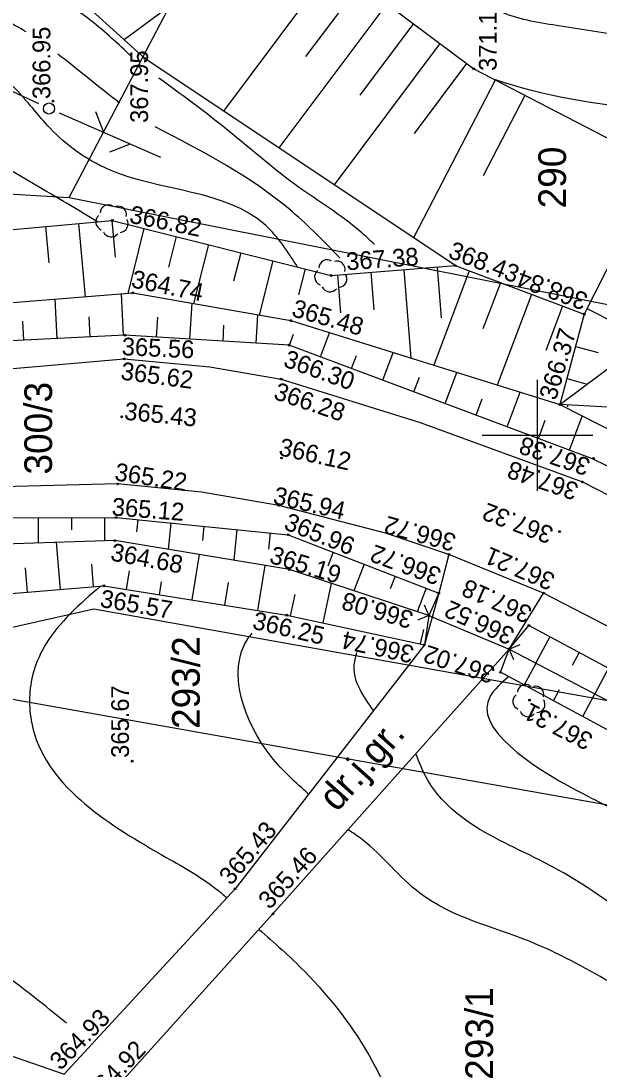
# Model space of a CAD drawing. Extents: x 4635329 to 4651863, y 5356628 to 5367582.
# Drawn here: x 4651263.7 to 4651289.79, y 5356677.75 to 5356725.05 of the extents above; entities that cross this region are included whole.
import ezdxf

# ---------------------------------------------------------------- set-up
doc = ezdxf.new("R2010")
doc.units = 0
for name, color, linetype in [('Level 20', 7, 'Continuous'), ('Level 21', 7, 'Continuous'), ('Level 24', 7, 'Continuous'), ('Level 32', 7, 'Continuous'), ('Level 4', 7, 'Continuous'), ('Level 44', 7, 'Continuous'), ('Level 45', 7, 'Continuous'), ('Level 46', 7, 'Continuous'), ('Level 48', 7, 'Continuous'), ('Level 5', 7, 'Continuous'), ('Level 50', 7, 'Continuous'), ('Level 55', 7, 'Continuous'), ('Level 60', 7, 'Continuous')]:
    doc.layers.add(name, color=color, linetype=linetype)

msp = doc.modelspace()

# ---------------------------------------------------------------- linework, layer by layer
at = {"layer": 'Level 20'}
for p, q in [((4651255.835, 5356708.727), (4651268.355, 5356709.797)), ((4651289.035, 5356704.247), (4651300.075, 5356698.607))]:
    msp.add_line(p, q, dxfattribs=at)
for points in [[(4651268.355, 5356709.797), (4651272.22, 5356709.442), (4651275.445, 5356708.887)], [(4651275.445, 5356708.887), (4651281.72, 5356706.931), (4651289.035, 5356704.247)], [(4651311.985, 5356685.667), (4651297.855, 5356693.767), (4651287.285, 5356699.227), (4651283.015, 5356700.977), (4651280.145, 5356701.933), (4651275.335, 5356703.187), (4651271.856, 5356703.778), (4651268.065, 5356704.157), (4651257.665, 5356703.887), (4651250.625, 5356702.417), (4651229.275, 5356695.327), (4651226.835, 5356694.217), (4651221.145, 5356692.917), (4651218.085, 5356691.717)], [(4651283.015, 5356700.977), (4651282.555, 5356699.227), (4651281.905, 5356696.897), (4651273.365, 5356685.887), (4651265.645, 5356677.517)], [(4651267.255, 5356676.097), (4651275.075, 5356684.757), (4651285.735, 5356696.707), (4651287.285, 5356699.227)], [(4651256.195, 5356680.807), (4651265.645, 5356677.517)]]:
    msp.add_lwpolyline(points, dxfattribs=at)
at = {"layer": 'Level 24'}
for p, q in [((4651281.903, 5356698.707), (4651282.105, 5356698.217)), ((4651282.105, 5356698.217), (4651281.615, 5356698.015)), ((4651282.105, 5356698.217), (4651285.735, 5356696.707)), ((4651285.735, 5356696.707), (4651286.225, 5356696.909)), ((4651285.937, 5356696.217), (4651285.735, 5356696.707))]:
    msp.add_line(p, q, dxfattribs=at)
at = {"layer": 'Level 32'}
for p, q in [((4651264.512, 5356721.308), (4651259.978, 5356723.417)), ((4651265.423, 5356720.897), (4651270.006, 5356718.896)), ((4651267.446, 5356720.014), (4651267.081, 5356720.945)), ((4651268.631, 5356719.496), (4651267.7, 5356719.131))]:
    msp.add_line(p, q, dxfattribs=at)
msp.add_circle((4651264.965, 5356721.097), 0.25, dxfattribs=at)
at = {"layer": 'Level 4'}
for p, q in [((4651265.88, 5356717.076), (4651276.761, 5356737.838)), ((4651262.484, 5356717.287), (4651265.88, 5356717.076)), ((4651265.88, 5356717.076), (4651293.053, 5356711.679)), ((4651266.997, 5356698.5), (4651255.225, 5356695.887)), ((4651294.579, 5356693.592), (4651266.997, 5356698.5)), ((4651255.225, 5356695.887), (4651299.165, 5356688.087))]:
    msp.add_line(p, q, dxfattribs=at)
at = {"layer": 'Level 44'}
for centre in [(4651269.285, 5356723.357), (4651284.135, 5356722.887), (4651265.147, 5356721.43), (4651267.825, 5356716.047), (4651277.695, 5356713.567), (4651283.295, 5356714.007), (4651268.755, 5356712.777), (4651289.115, 5356711.817), (4651275.875, 5356711.527), (4651268.385, 5356710.867), (4651275.805, 5356710.417), (4651268.355, 5356709.797), (4651275.445, 5356708.887), (4651288.015, 5356707.737), (4651268.245, 5356707.187), (4651275.465, 5356705.327), (4651289.535, 5356705.308), (4651268.065, 5356704.157), (4651289.035, 5356704.247), (4651275.335, 5356703.187), (4651267.995, 5356702.637), (4651275.755, 5356701.867), (4651288.005, 5356702.007), (4651267.935, 5356701.597), (4651283.015, 5356700.977), (4651275.815, 5356700.297), (4651267.445, 5356699.557), (4651282.555, 5356699.227), (4651287.285, 5356699.227), (4651275.705, 5356698.237), (4651282.105, 5356698.217), (4651286.625, 5356697.767), (4651281.905, 5356696.897), (4651285.735, 5356696.707), (4651285.335, 5356695.657), (4651286.645, 5356694.397), (4651268.725, 5356691.647), (4651273.365, 5356685.887), (4651275.075, 5356684.757)]:
    msp.add_circle(centre, 0.04, dxfattribs=at)
at = {"layer": 'Level 46'}
for points in [[(4651267.161, 5356715.987), (4651264.708, 5356717.442), (4651260.614, 5356719.868), (4651257.43, 5356722.141), (4651254.792, 5356725.021), (4651252.517, 5356728.872), (4651246.741, 5356739.5), (4651245.898, 5356740.725)], [(4651298.334, 5356723.071), (4651293.949, 5356723.874), (4651287.864, 5356724.843), (4651285.317, 5356725.479), (4651282.527, 5356727.511), (4651276.752, 5356731.958), (4651274.72, 5356734.595), (4651272.415, 5356737.688), (4651271.657, 5356740.507), (4651271.694, 5356740.701)], [(4651263.931, 5356724.554), (4651261.972, 5356725.806), (4651257.58, 5356731.092)], [(4651268.687, 5356723.452), (4651266.865, 5356725.056), (4651263.408, 5356727.482), (4651263.267, 5356727.595)], [(4651276.186, 5356713.946), (4651274.753, 5356715.814), (4651267.627, 5356718.36), (4651265.018, 5356720.21), (4651263.442, 5356721.998), (4651259.59, 5356724.848), (4651257.237, 5356726.91)], [(4651268.154, 5356721.342), (4651268.067, 5356721.41), (4651265.371, 5356723.557)], [(4651279.659, 5356714.965), (4651278.996, 5356715.567), (4651276.206, 5356717.568), (4651272.809, 5356720.297), (4651269.931, 5356722.46)], [(4651295.563, 5356720.909), (4651292.254, 5356721.058), (4651285.582, 5356722.24), (4651285.048, 5356722.414)], [(4651278.086, 5356714.362), (4651275.943, 5356716.443), (4651269.759, 5356720.271)], [(4651267.298, 5356699.545), (4651264.801, 5356696.886), (4651264.194, 5356695.37), (4651264.255, 5356693.066), (4651270.259, 5356687.306), (4651272.625, 5356685.79), (4651272.99, 5356685.481)], [(4651276.684, 5356690.165), (4651274.991, 5356691.857), (4651273.96, 5356697.193), (4651274.134, 5356697.423)], [(4651279.608, 5356693.936), (4651278.738, 5356695.917), (4651278.857, 5356696.551)], [(4651285.707, 5356695.457), (4651284.877, 5356694.586), (4651288.759, 5356690.341), (4651291.246, 5356689.007), (4651295.31, 5356684.945), (4651298.181, 5356680.494)], [(4651300.394, 5356650.538), (4651298.071, 5356657.119), (4651297.283, 5356664.395), (4651297.525, 5356670.398), (4651297.222, 5356675.491), (4651291.339, 5356684.404), (4651287.093, 5356687.193), (4651283.575, 5356689.133), (4651281.998, 5356690.892), (4651281.523, 5356691.985)], [(4651265.764, 5356679.82), (4651263.304, 5356681.756), (4651255.783, 5356687.85), (4651255.142, 5356688.646)], [(4651290.286, 5356681.678), (4651286.676, 5356683.504), (4651281.703, 5356685.687), (4651279.095, 5356688.112), (4651278.462, 5356688.554)], [(4651274.444, 5356684.058), (4651276.507, 5356682.152), (4651281.177, 5356673.421), (4651281.298, 5356669.601), (4651282.502, 5356660.721), (4651283.836, 5356656.113), (4651284.685, 5356650.656), (4651285.015, 5356650.008)]]:
    msp.add_spline(points, degree=3, dxfattribs=at)
at = {"layer": 'Level 48'}
for p, q in [((4651275.412, 5356729.428), (4651268.359, 5356724.195)), ((4651277.806, 5356727.623), (4651272.839, 5356720.985)), ((4651279.007, 5356726.724), (4651276.548, 5356723.438)), ((4651280.208, 5356725.826), (4651275.338, 5356719.317)), ((4651281.409, 5356724.927), (4651278.998, 5356721.705)), ((4651282.61, 5356724.028), (4651277.837, 5356717.65)), ((4651283.811, 5356723.13), (4651281.449, 5356719.973)), ((4651285.107, 5356722.383), (4651281.415, 5356715.262)), ((4651286.439, 5356721.692), (4651284.555, 5356718.058)), ((4651267.799, 5356716.045), (4651267.95, 5356714.384)), ((4651264.811, 5356715.773), (4651264.961, 5356714.129)), ((4651266.305, 5356715.909), (4651266.606, 5356712.604)), ((4651269.254, 5356715.688), (4651268.518, 5356712.757)), ((4651270.709, 5356715.322), (4651270.362, 5356713.939)), ((4651272.164, 5356714.957), (4651271.495, 5356712.296)), ((4651273.619, 5356714.591), (4651273.298, 5356713.314)), ((4651275.074, 5356714.226), (4651274.458, 5356711.776)), ((4651276.528, 5356713.86), (4651276.233, 5356712.684)), ((4651277.991, 5356713.59), (4651278.126, 5356711.881)), ((4651279.487, 5356713.708), (4651279.62, 5356712.012)), ((4651280.982, 5356713.825), (4651281.296, 5356709.835)), ((4651283.931, 5356713.768), (4651282.33, 5356709.512)), ((4651282.477, 5356713.943), (4651282.658, 5356711.648)), ((4651285.335, 5356713.239), (4651284.55, 5356711.152)), ((4651268.329, 5356710.864), (4651268.235, 5356712.735)), ((4651286.739, 5356712.711), (4651285.198, 5356708.616)), ((4651265.332, 5356710.715), (4651265.244, 5356712.495)), ((4651271.323, 5356710.689), (4651271.422, 5356712.309)), ((4651288.143, 5356712.183), (4651287.388, 5356710.176)), ((4651266.831, 5356710.789), (4651266.785, 5356711.702)), ((4651274.318, 5356710.507), (4651274.395, 5356711.787)), ((4651289.243, 5356712.07), (4651290.605, 5356711.379)), ((4651263.834, 5356710.64), (4651263.791, 5356711.508)), ((4651269.826, 5356710.78), (4651269.88, 5356711.675)), ((4651272.821, 5356710.598), (4651272.864, 5356711.323)), ((4651275.814, 5356710.413), (4651276.004, 5356710.921)), ((4651277.219, 5356709.888), (4651277.628, 5356710.98)), ((4651288.722, 5356710.36), (4651289.753, 5356710.082)), ((4651278.624, 5356709.362), (4651278.843, 5356709.947)), ((4651280.029, 5356708.837), (4651280.496, 5356710.084)), ((4651281.434, 5356708.311), (4651281.682, 5356708.974)), ((4651282.839, 5356707.786), (4651283.364, 5356709.189)), ((4651288.332, 5356708.912), (4651289.255, 5356708.663)), ((4651284.244, 5356707.26), (4651284.521, 5356708.001)), ((4651285.649, 5356706.735), (4651286.232, 5356708.294)), ((4651288.371, 5356707.718), (4651288.366, 5356707.639)), ((4651287.054, 5356706.209), (4651287.36, 5356707.027)), ((4651288.459, 5356705.684), (4651289.034, 5356707.22)), ((4651264.477, 5356702.63), (4651264.479, 5356701.485)), ((4651265.977, 5356702.633), (4651265.978, 5356702.083)), ((4651267.477, 5356702.636), (4651267.479, 5356701.583)), ((4651268.972, 5356702.54), (4651268.918, 5356701.992)), ((4651270.465, 5356702.392), (4651270.346, 5356701.199)), ((4651271.957, 5356702.244), (4651271.893, 5356701.599)), ((4651273.45, 5356702.096), (4651273.312, 5356700.71)), ((4651274.943, 5356701.948), (4651274.869, 5356701.206)), ((4651265.485, 5356699.395), (4651265.311, 5356701.512)), ((4651271.428, 5356698.921), (4651271.755, 5356700.967)), ((4651277.791, 5356701.077), (4651277.544, 5356700.442)), ((4651263.99, 5356699.272), (4651263.9, 5356700.368)), ((4651266.98, 5356699.519), (4651266.896, 5356700.54)), ((4651274.39, 5356698.447), (4651274.715, 5356700.479)), ((4651279.189, 5356700.534), (4651278.724, 5356699.335)), ((4651268.466, 5356699.394), (4651268.6, 5356700.233)), ((4651280.587, 5356699.991), (4651280.368, 5356699.427)), ((4651269.947, 5356699.157), (4651270.041, 5356699.745)), ((4651272.909, 5356698.684), (4651273.072, 5356699.703)), ((4651277.336, 5356697.884), (4651277.721, 5356699.667)), ((4651281.986, 5356699.448), (4651281.576, 5356698.392)), ((4651275.87, 5356698.201), (4651276.079, 5356699.171)), ((4651281.734, 5356696.934), (4651281.876, 5356697.59)), ((4651287.572, 5356697.258), (4651286.939, 5356696.079)), ((4651288.894, 5356696.548), (4651288.581, 5356695.966)), ((4651286.41, 5356695.079), (4651286.946, 5356696.075)), ((4651290.215, 5356695.839), (4651289.598, 5356694.69)), ((4651287.731, 5356694.368), (4651288.004, 5356694.874)), ((4651289.052, 5356693.657), (4651289.606, 5356694.686))]:
    msp.add_line(p, q, dxfattribs=at)
for points in [[(4651283.295, 5356714.007), (4651269.285, 5356723.357), (4651257.365, 5356734.147), (4651256.135, 5356741.187)], [(4651256.135, 5356741.187), (4651268.995, 5356738.077), (4651275.435, 5356729.397), (4651284.135, 5356722.887), (4651292.525, 5356718.537)], [(4651247.285, 5356725.877), (4651243.735, 5356717.987), (4651242.545, 5356711.907), (4651255.405, 5356714.917), (4651267.825, 5356716.047), (4651277.695, 5356713.567), (4651283.295, 5356714.007), (4651289.115, 5356711.817), (4651288.015, 5356707.737)], [(4651292.525, 5356718.537), (4651289.115, 5356711.817)], [(4651240.535, 5356708.097), (4651248.565, 5356709.997), (4651255.655, 5356711.727), (4651268.755, 5356712.777), (4651275.875, 5356711.527), (4651288.015, 5356707.737), (4651290.775, 5356706.337), (4651301.395, 5356700.527), (4651315.355, 5356692.437)], [(4651314.845, 5356691.477), (4651300.685, 5356699.827), (4651289.5, 5356705.294), (4651275.805, 5356710.417), (4651268.385, 5356710.867), (4651255.355, 5356710.217), (4651248.785, 5356708.807), (4651240.305, 5356706.817)], [(4651298.855, 5356707.147), (4651288.015, 5356707.737)], [(4651229.735, 5356694.137), (4651251.025, 5356700.977), (4651258.145, 5356702.617), (4651267.995, 5356702.637), (4651275.755, 5356701.867), (4651282.555, 5356699.227)], [(4651282.105, 5356698.217), (4651275.815, 5356700.297), (4651267.935, 5356701.597), (4651258.365, 5356701.287), (4651251.215, 5356699.707), (4651230.125, 5356693.117)], [(4651230.585, 5356692.267), (4651234.725, 5356691.737), (4651252.495, 5356697.007), (4651260.165, 5356698.957), (4651267.445, 5356699.557), (4651275.705, 5356698.237), (4651281.905, 5356696.897)], [(4651282.555, 5356699.227), (4651282.105, 5356698.217), (4651281.905, 5356696.897)], [(4651285.335, 5356695.657), (4651285.735, 5356696.707), (4651286.625, 5356697.767)], [(4651311.435, 5356684.627), (4651297.255, 5356692.057), (4651286.625, 5356697.767)], [(4651285.735, 5356696.707), (4651296.535, 5356691.067), (4651310.765, 5356683.347)], [(4651310.375, 5356682.647), (4651297.845, 5356688.927), (4651285.335, 5356695.657)]]:
    msp.add_lwpolyline(points, dxfattribs=at)
at = {"layer": 'Level 50'}
msp.add_line((4651288.015, 5356707.737), (4651296.455, 5356714.037), dxfattribs=at)
at = {"layer": 'Level 55'}
for centre in [(4651267.825, 5356716.047), (4651277.695, 5356713.567), (4651286.645, 5356694.397)]:
    msp.add_circle(centre, 0.045, dxfattribs=at)
for centre, start, end in [((4651267.647, 5356716.377), 58.348, 178.132), ((4651268.084, 5356716.318), 346.3906, 106.042), ((4651267.456, 5356715.98), 130.3488, 250.1306), ((4651268.163, 5356715.884), 274.3875, 34.0933), ((4651267.775, 5356715.676), 202.4389, 322.0902), ((4651277.517, 5356713.897), 58.348, 178.132), ((4651277.954, 5356713.838), 346.3906, 106.042), ((4651277.326, 5356713.5), 130.3488, 250.1306), ((4651278.033, 5356713.404), 274.3875, 34.0933), ((4651277.645, 5356713.196), 202.4389, 322.0902), ((4651286.482, 5356694.735), 55.8648, 175.6487), ((4651286.916, 5356694.656), 343.9073, 103.5587), ((4651286.273, 5356694.346), 127.8655, 247.6473), ((4651286.975, 5356694.22), 271.9043, 31.61), ((4651286.578, 5356694.028), 199.9556, 319.607)]:
    msp.add_arc(centre, 0.375, start, end, dxfattribs=at)
at = {"layer": 'Level 60'}
for p, q in [((4651287.015, 5356703.847), (4651287.015, 5356708.847)), ((4651289.515, 5356706.347), (4651284.515, 5356706.347))]:
    msp.add_line(p, q, dxfattribs=at)

# ---------------------------------------------------------------- texts
at = {"layer": 'Level 21'}
msp.add_text('dr.j.gr.', height=1.25, rotation=48.2654, dxfattribs=at).set_placement((4651277.955, 5356689.315))
at = {"layer": 'Level 45'}
for s, rotation, p in [('371.12', 90, (4651285.167, 5356722.795)), ('366.95', 90, (4651265.027, 5356721.52)), ('367.95', 90, (4651269.438, 5356720.448)), ('366.82', 348.5428, (4651268.557, 5356715.95)), ('368.43', 339.025, (4651282.936, 5356714.381)), ('367.38', 4.1398, (4651278.405, 5356713.794)), ('364.74', 348.5999, (4651268.638, 5356713.036)), ('368.84', 159.7357, (4651289.346, 5356712.724)), ('365.48', 344.0087, (4651275.875, 5356711.738)), ('365.56', 357.4584, (4651268.238, 5356709.968)), ('366.37', 73.4909, (4651287.837, 5356707.89)), ('366.30', 340.2433, (4651275.496, 5356709.477)), ('365.62', 352.4822, (4651268.172, 5356708.872)), ('366.28', 341.4526, (4651275.059, 5356708.005)), ('365.43', 354.4555, (4651268.338, 5356707.058)), ('366.12', 347.6653, (4651275.295, 5356705.459)), ('367.38', 161.0643, (4651289.457, 5356705.259)), ('365.22', 351.3249, (4651267.895, 5356704.324)), ('367.48', 161.0643, (4651288.926, 5356704.154)), ('365.94', 347.1071, (4651275.04, 5356703.273)), ('365.12', 355.5805, (4651267.779, 5356702.74)), ('367.32', 159.4742, (4651287.793, 5356702.178)), ('365.96', 338.2468, (4651275.518, 5356702.136)), ('366.72', 164.8466, (4651283.395, 5356701.868)), ('364.68', 349.4792, (4651267.706, 5356700.71)), ('365.19', 342.7516, (4651274.867, 5356700.614)), ('366.72', 159.9867, (4651282.735, 5356700.321)), ('367.21', 156.9149, (4651287.868, 5356700.057)), ('367.18', 156.2552, (4651286.829, 5356698.571)), ('365.57', 350.3722, (4651267.233, 5356698.612)), ('366.08', 163.6546, (4651281.467, 5356698.372)), ('366.52', 155.8456, (4651286.043, 5356697.593)), ('366.25', 346.9832, (4651274.104, 5356697.629)), ('366.74', 167.7719, (4651281.487, 5356696.835)), ('367.02', 161.9685, (4651285.156, 5356695.89)), ('365.67', 90, (4651268.575, 5356691.797)), ('367.31', 152.9132, (4651289.582, 5356692.82)), ('365.43', 49.6872, (4651273.18, 5356686.001)), ('365.46', 47.3586, (4651274.922, 5356684.917)), ('364.93', 45.4309, (4651265.488, 5356677.658)), ('364.92', 45.8455, (4651267.116, 5356676.214))]:
    msp.add_text(s, height=0.8, rotation=rotation, dxfattribs=at).set_placement(p)
at = {"layer": 'Level 5'}
for s, p in [('290', (4651288.3, 5356716.589)), ('300/3', (4651265.106, 5356704.579)), ('293/2', (4651271.772, 5356693.099)), ('293/1', (4651285.008, 5356677.266))]:
    msp.add_text(s, height=1.25, rotation=90, dxfattribs=at).set_placement(p)

doc.saveas('drawing.dxf')
